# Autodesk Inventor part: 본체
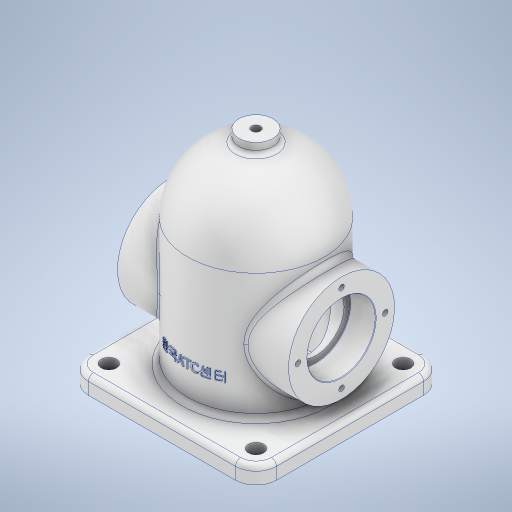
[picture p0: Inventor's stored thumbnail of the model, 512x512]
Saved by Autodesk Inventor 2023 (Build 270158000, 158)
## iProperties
Created: 2025-04
Part Number: 본체
Material: 알루미늄 6061
Document SubType Name: Modeling
Designer: Admin
Density: 2.7 g/cm^3
Appearance: 알루미늄 - 평지
Author: Admin
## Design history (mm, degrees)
node "작업 평면1"
sketch "스케치1"
  geometry: L1 (-55, 55)-(55, 55); L2 (55, 55)-(55, -55); L3 (55, -55)-(-55, -55); L4 (-55, -55)-(-55, 55); L5 (-55, 55)-(55, -55); L6 (55, 55)-(-55, -55); 1 further point
  constraints: 12 end point, 2 midpoint, 2 parallel, 1 horizontal, 1 perpendicular
  dimensions: "d1" = 110 distance of L2.end L3.end; "d2" = 110 distance of L1.end L2.end
extrude "돌출1" new body sketch "스케치1" distance "d3" = 10; taper "d4" = 0 deg
sketch "스케치2"
  geometry: L1 (43, -43)-(-43, -43); L2 (-43, -43)-(-43, 43); L3 (-43, 43)-(43, 43); L4 (43, 43)-(43, -43); L5 (43, -43)-(-43, 43); L6 (-43, -43)-(43, 43); 5 further points
  constraints: 12 end point, 4 coincident, 2 midpoint, 2 parallel, 1 horizontal, 1 perpendicular
  dimensions: "d5" = 86 distance of L2.end L3.end; "d6" = 86 distance of L1.end L2.end
hole "구멍1" sketch "스케치2" at (-43, -43), (-43, 43), (43, -43), (43, 43) diameter "d7" = 9; stored, may be unused: countersink angle "d11" = 90 deg, drill point angle "d13" = 0 deg; dims "d8" = 8, "d9" = 4, "d10" = 2, "d12" = 10
sketch "스케치12"
  geometry: C1 r 40 at (0, 0); 1 further point
  constraints: 1 centre point, 1 coincident
  dimensions: "d50" = 40 radius of C1
extrude "돌출4" join sketch "스케치12" distance "d51" = 74; taper "d52" = 0 deg
sketch "스케치15"
  geometry: L1 (36, -40)-(36, 40) reference; L2 (-72.8, 0)-(100.8, 0) reference; A1 r 40 centre (36, 0) between (36, -40) and (36, 40); 1 further point
  constraints: 2 point on circle, 1 centre point, 1 midpoint
revolve "회전3" sketch "스케치15" stored, may be unused: angle "d53" = 90 deg
node "작업 평면3"
sketch "스케치17"
  geometry: L1 (-48, 55)-(-48, -55) reference; C1 r 31 at (0, 0); 1 further point
  constraints: 1 centre point, 1 coincident
  dimensions: "d61" = 62 diameter of C1; "d62" = 48 distance from line of L1 C1.centre
extrude "돌출6" join sketch "스케치17" stored distance "d63" = 32; taper "d64" = 0 deg
sketch "스케치18"
  geometry: C1 r 20 at (0, 0); 1 further point
  constraints: 1 centre point, 1 coincident
  dimensions: "d65" = 40 diameter of C1
extrude "돌출7" cut sketch "스케치18" distance "d66" = 15; taper "d67" = 0 deg
sketch "스케치20"
  geometry: L1 (-40, -38)-(-40, 36) reference; L2 (40, -38)-(40, 36) reference; L3 (-32, 36)-(-32, -48); L4 (55, -48)-(-55, -48) reference; L5 (0, -72.8)-(0, 100.8) reference; L6 (0, 68)-(0, -48); A1 r 40 centre (0, 36) between (40, 36) and (-40, 36) reference; A2 r 32 centre (0, 36) between (0, 68) and (-32, 36); 1 further point
  constraints: 4 end point, 3 point on line, 2 point on circle, 1 centre point, 1 midpoint, 1 vertical
  dimensions: "d69" = 32 radius of A2; "d70" = 8 distance between parallel lines of L1 L3
revolve "회전4" sketch "스케치20" stored, may be unused: angle "d71" = 360 deg
sketch "스케치21"
  geometry: C1 r 16.5 at (0, 0); 1 further point
  constraints: 1 centre point, 1 coincident
  dimensions: "d72" = 33 diameter of C1
extrude "돌출8" cut sketch "스케치21" stored distance "d73" = 15; taper "d74" = 0 deg
node "작업 평면4"
sketch "스케치22"
  geometry: C1 r 10 at (0, 0); 1 further point
  constraints: 1 centre point, 1 coincident
  dimensions: "d76" = 20 diameter of C1
extrude "돌출9" join sketch "스케치22" stored distance "d77" = 10; taper "d78" = 0 deg
sketch "스케치23"
  geometry: 2 further points
  constraints: 2 coincident
hole "구멍2" sketch "스케치23" at (0, 0) diameter "d79" = 5.1881; stored, may be unused: countersink angle "d83" = 90 deg, drill point angle "d85" = 0 deg; dims "d80" = 12, "d81" = 4, "d82" = 2, "d84" = 8
fillet "모깎기2" dims "d86" = 3
fillet "모깎기3" dims "d87" = 3
fillet "모깎기4" dims "d88" = 12
fillet "모깎기5" dims "d89" = 3
sketch "스케치24" dims "d90" = 51
  geometry: 3 further points
  constraints: 2 coincident, 2 vertical alignment, 2 other
hole "구멍3" sketch "스케치24" at (0, 25.5) diameter "d91" = 3.242; stored, may be unused: countersink angle "d95" = 90 deg, drill point angle "d97" = 118 deg; dims "d92" = 8, "d93" = 4, "d94" = 2, "d96" = 10
fillet "모깎기6" dims "d101" = 0.3
node "작업 평면5"
sketch "스케치25"
  geometry: L1 (-43, -48)-(43, -48) reference; 2 further points
  constraints: 1 vertical alignment, 1 other
  dimensions: "d103" = 30 distance from line of L1 point (0, -18)
feature "엠보싱1" sketch "스케치25" dims "d1" = 110, "d2" = 110, "d104" = 0.5, "d105" = 0
node "솔리드1"
mirror "미러1"
mirror "미러2"
mirror "미러3"
pattern_circular "원형 패턴1" dims angle "d99" = 360 deg
mirror "미러4"
feature "A9D066F2-1C7D-4E18-AEED-F7BC21143FA4" dims "d7" = 9, "d8" = 8, "d9" = 4, "d10" = 2, "d11" = 90 deg, "d12" = 10, "d13" = 0
other parameters: "d0" = -48, "d75" = -129
